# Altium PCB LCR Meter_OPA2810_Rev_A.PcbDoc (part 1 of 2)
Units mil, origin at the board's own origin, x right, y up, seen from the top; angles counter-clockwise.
Board outline 3760 x 2600 mil, 4 copper layers (L01_TOP, L02_GND, L03_PWR, L04_BOT), stack 62.234 mil thick; 153 components, 56 nets, 334 pads, 170 vias.
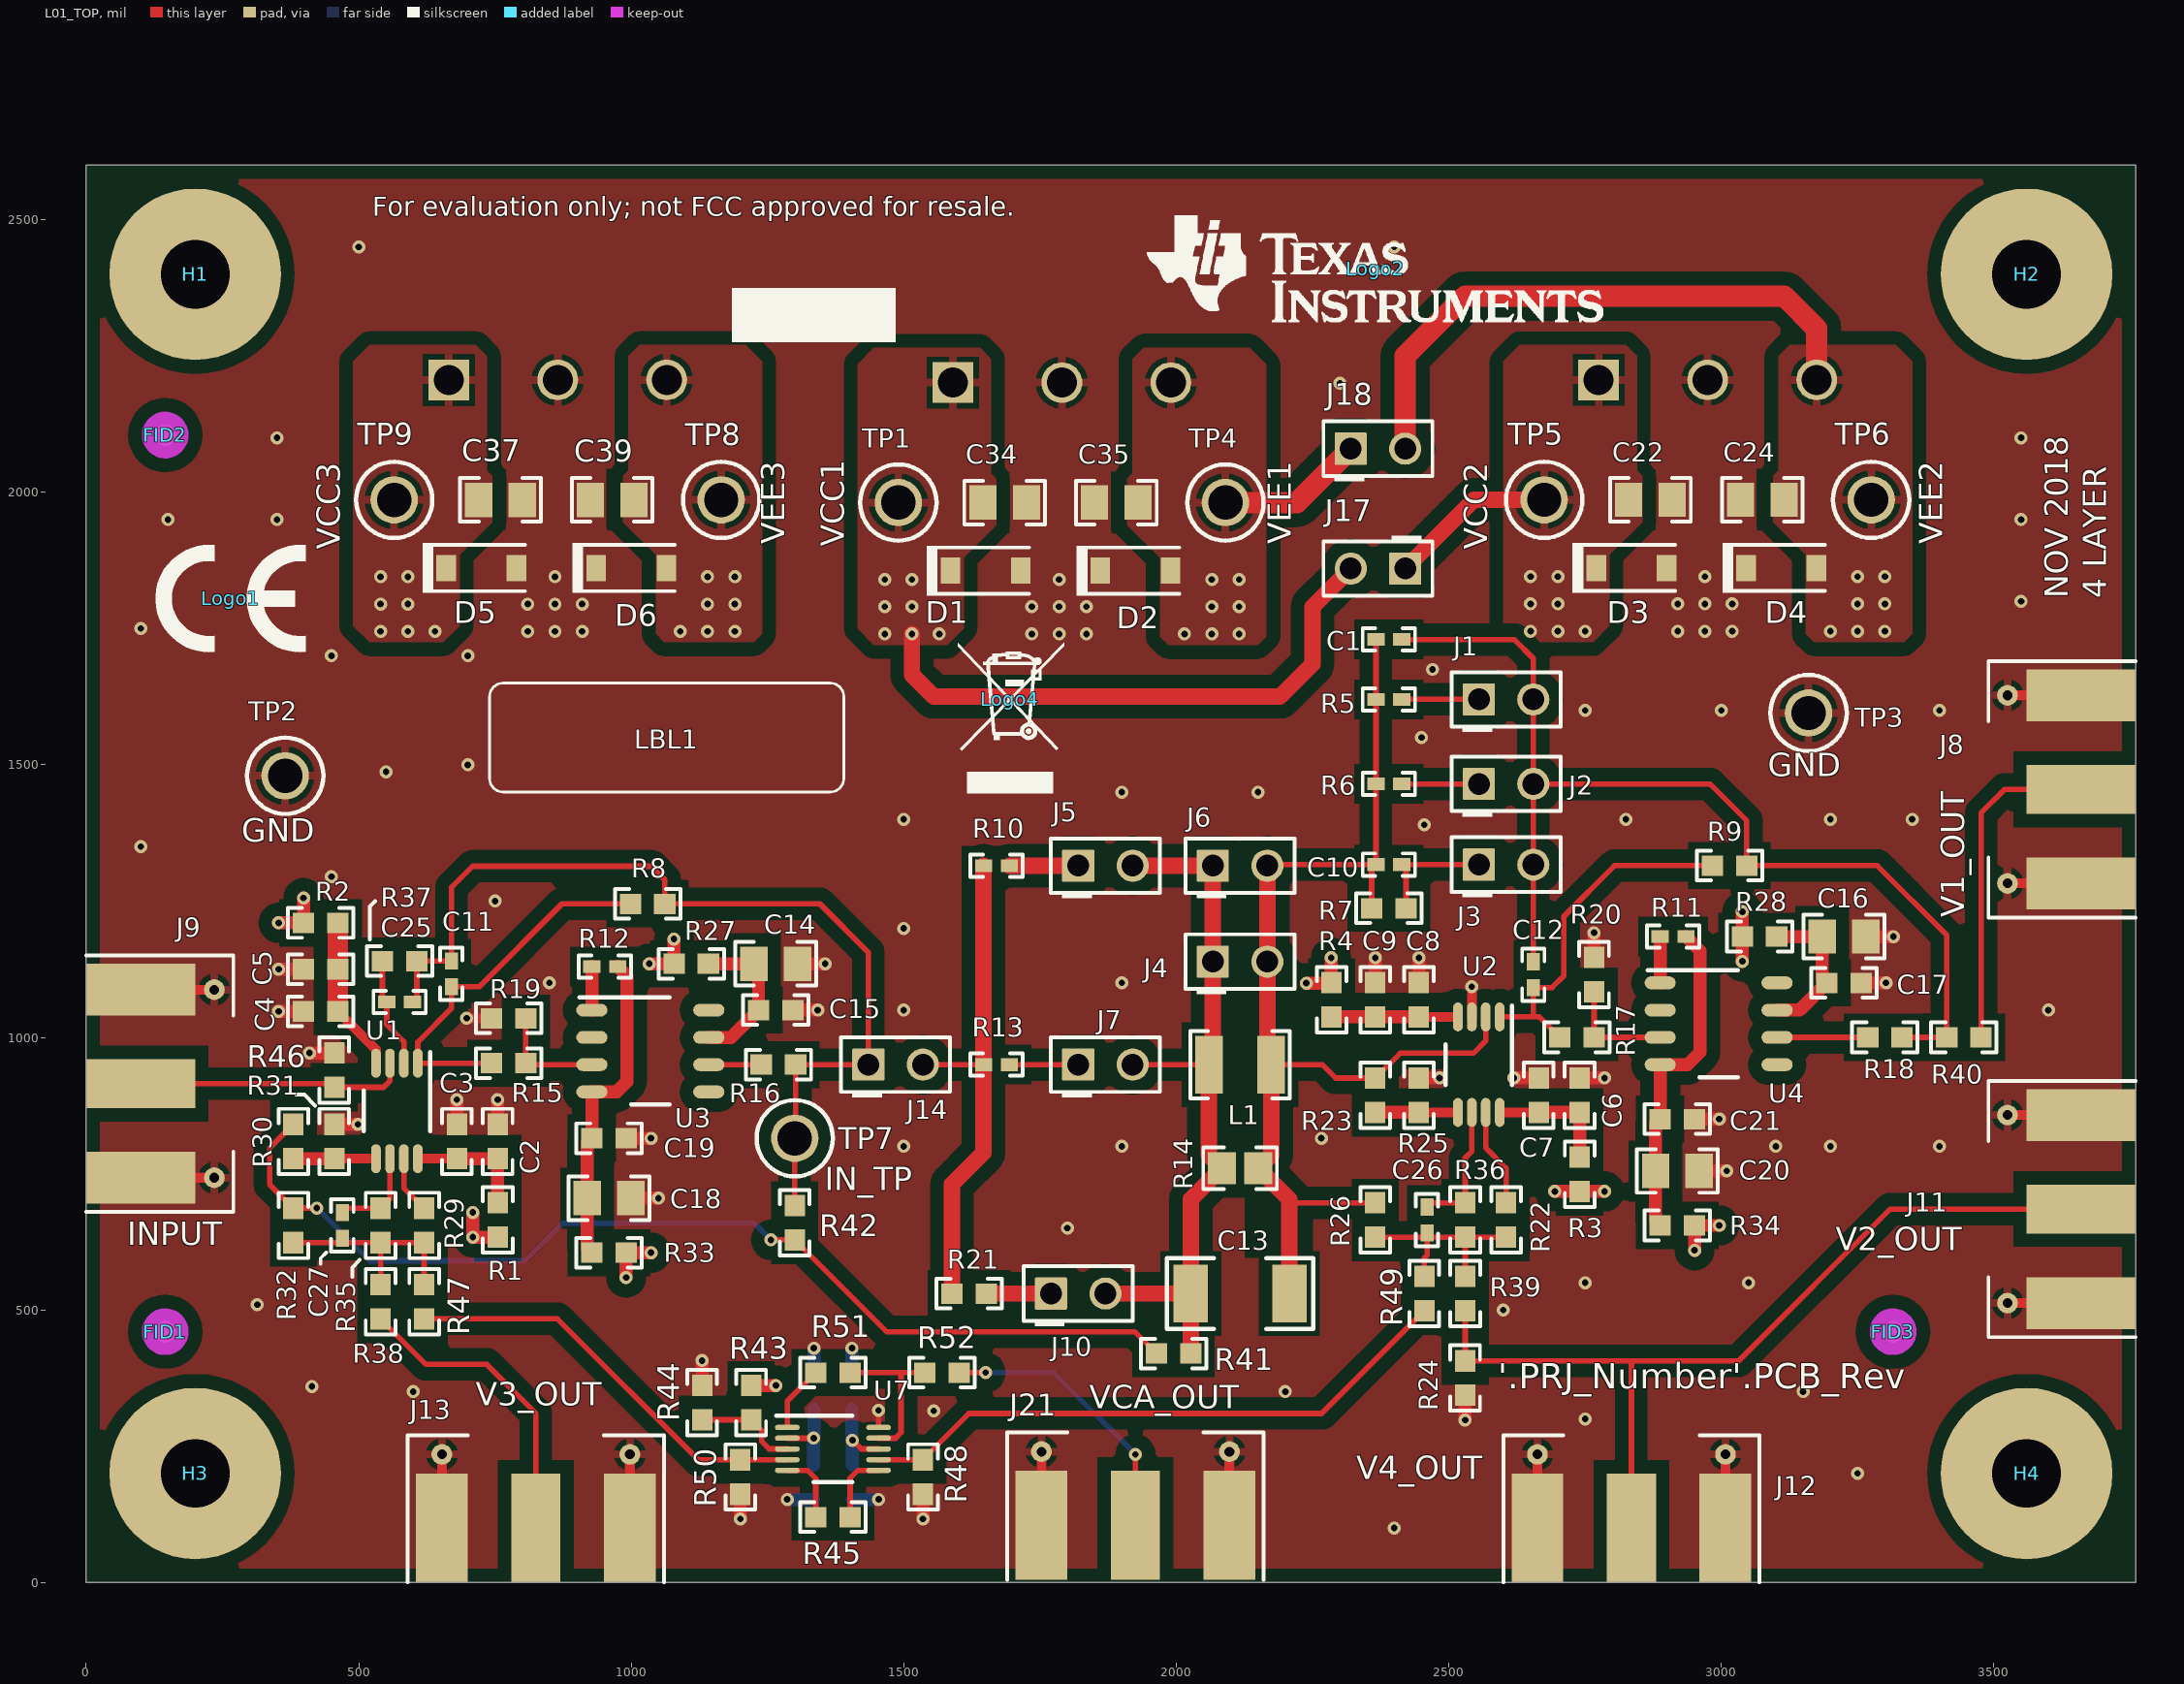
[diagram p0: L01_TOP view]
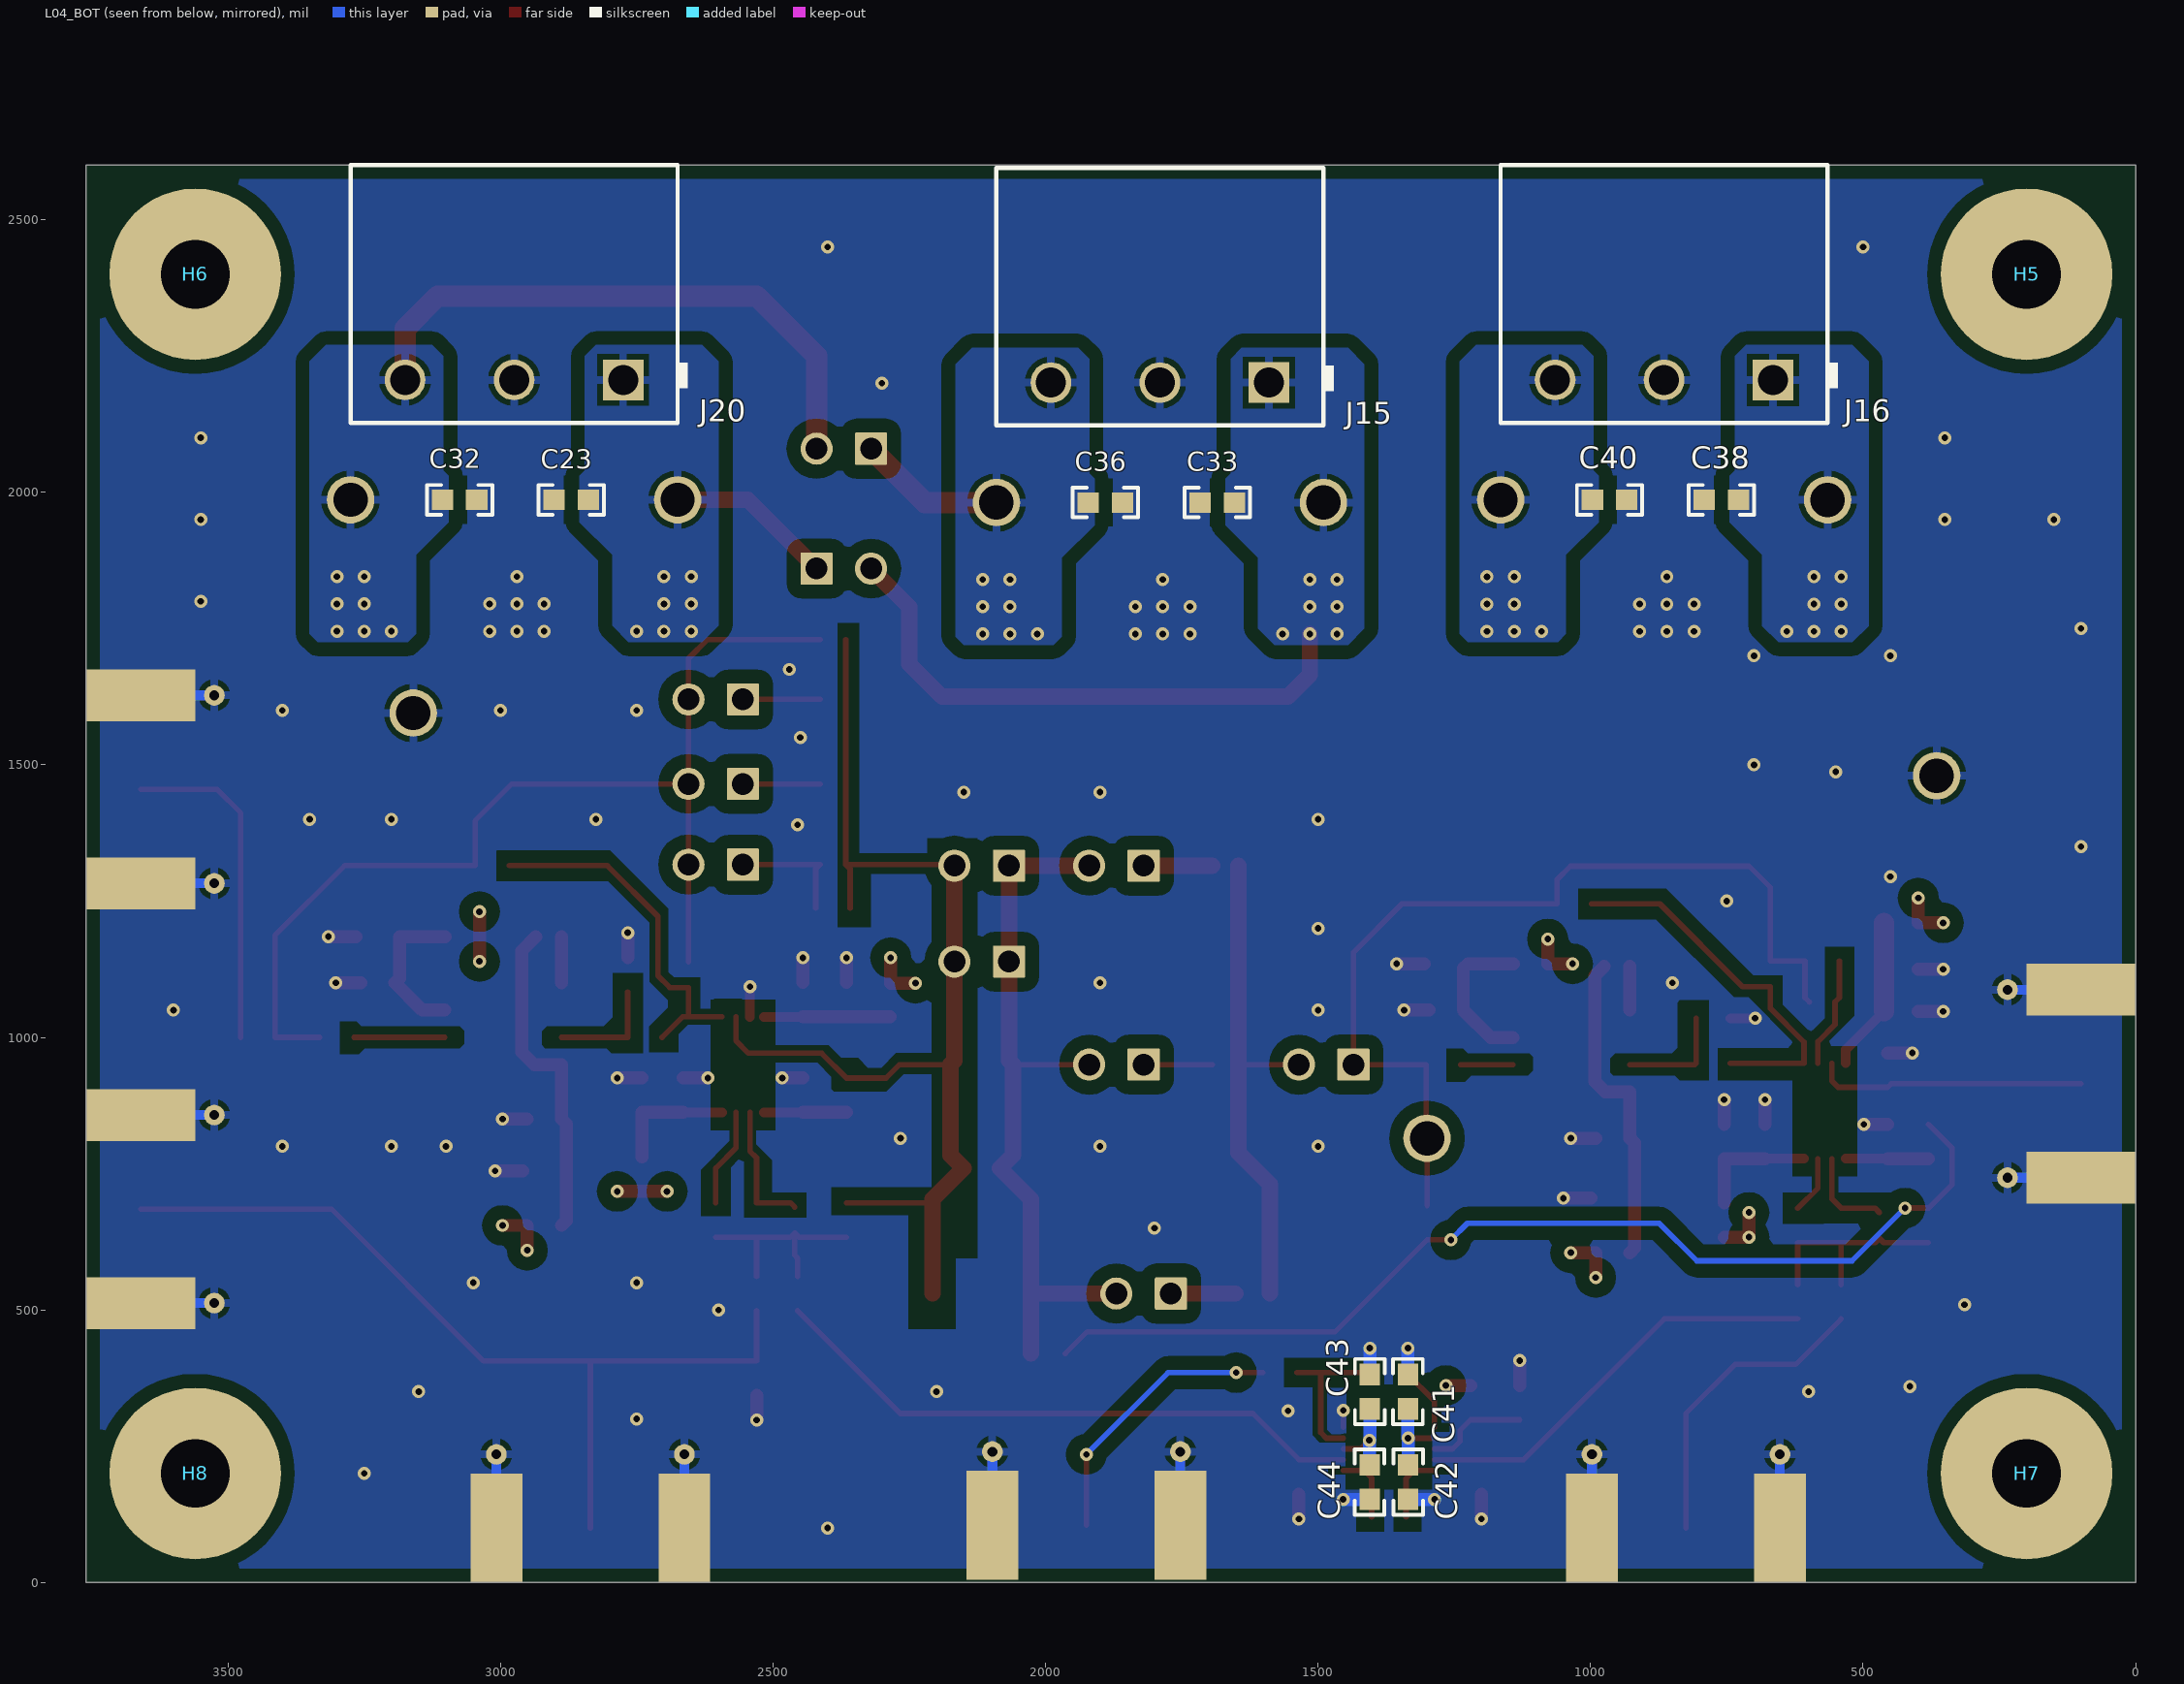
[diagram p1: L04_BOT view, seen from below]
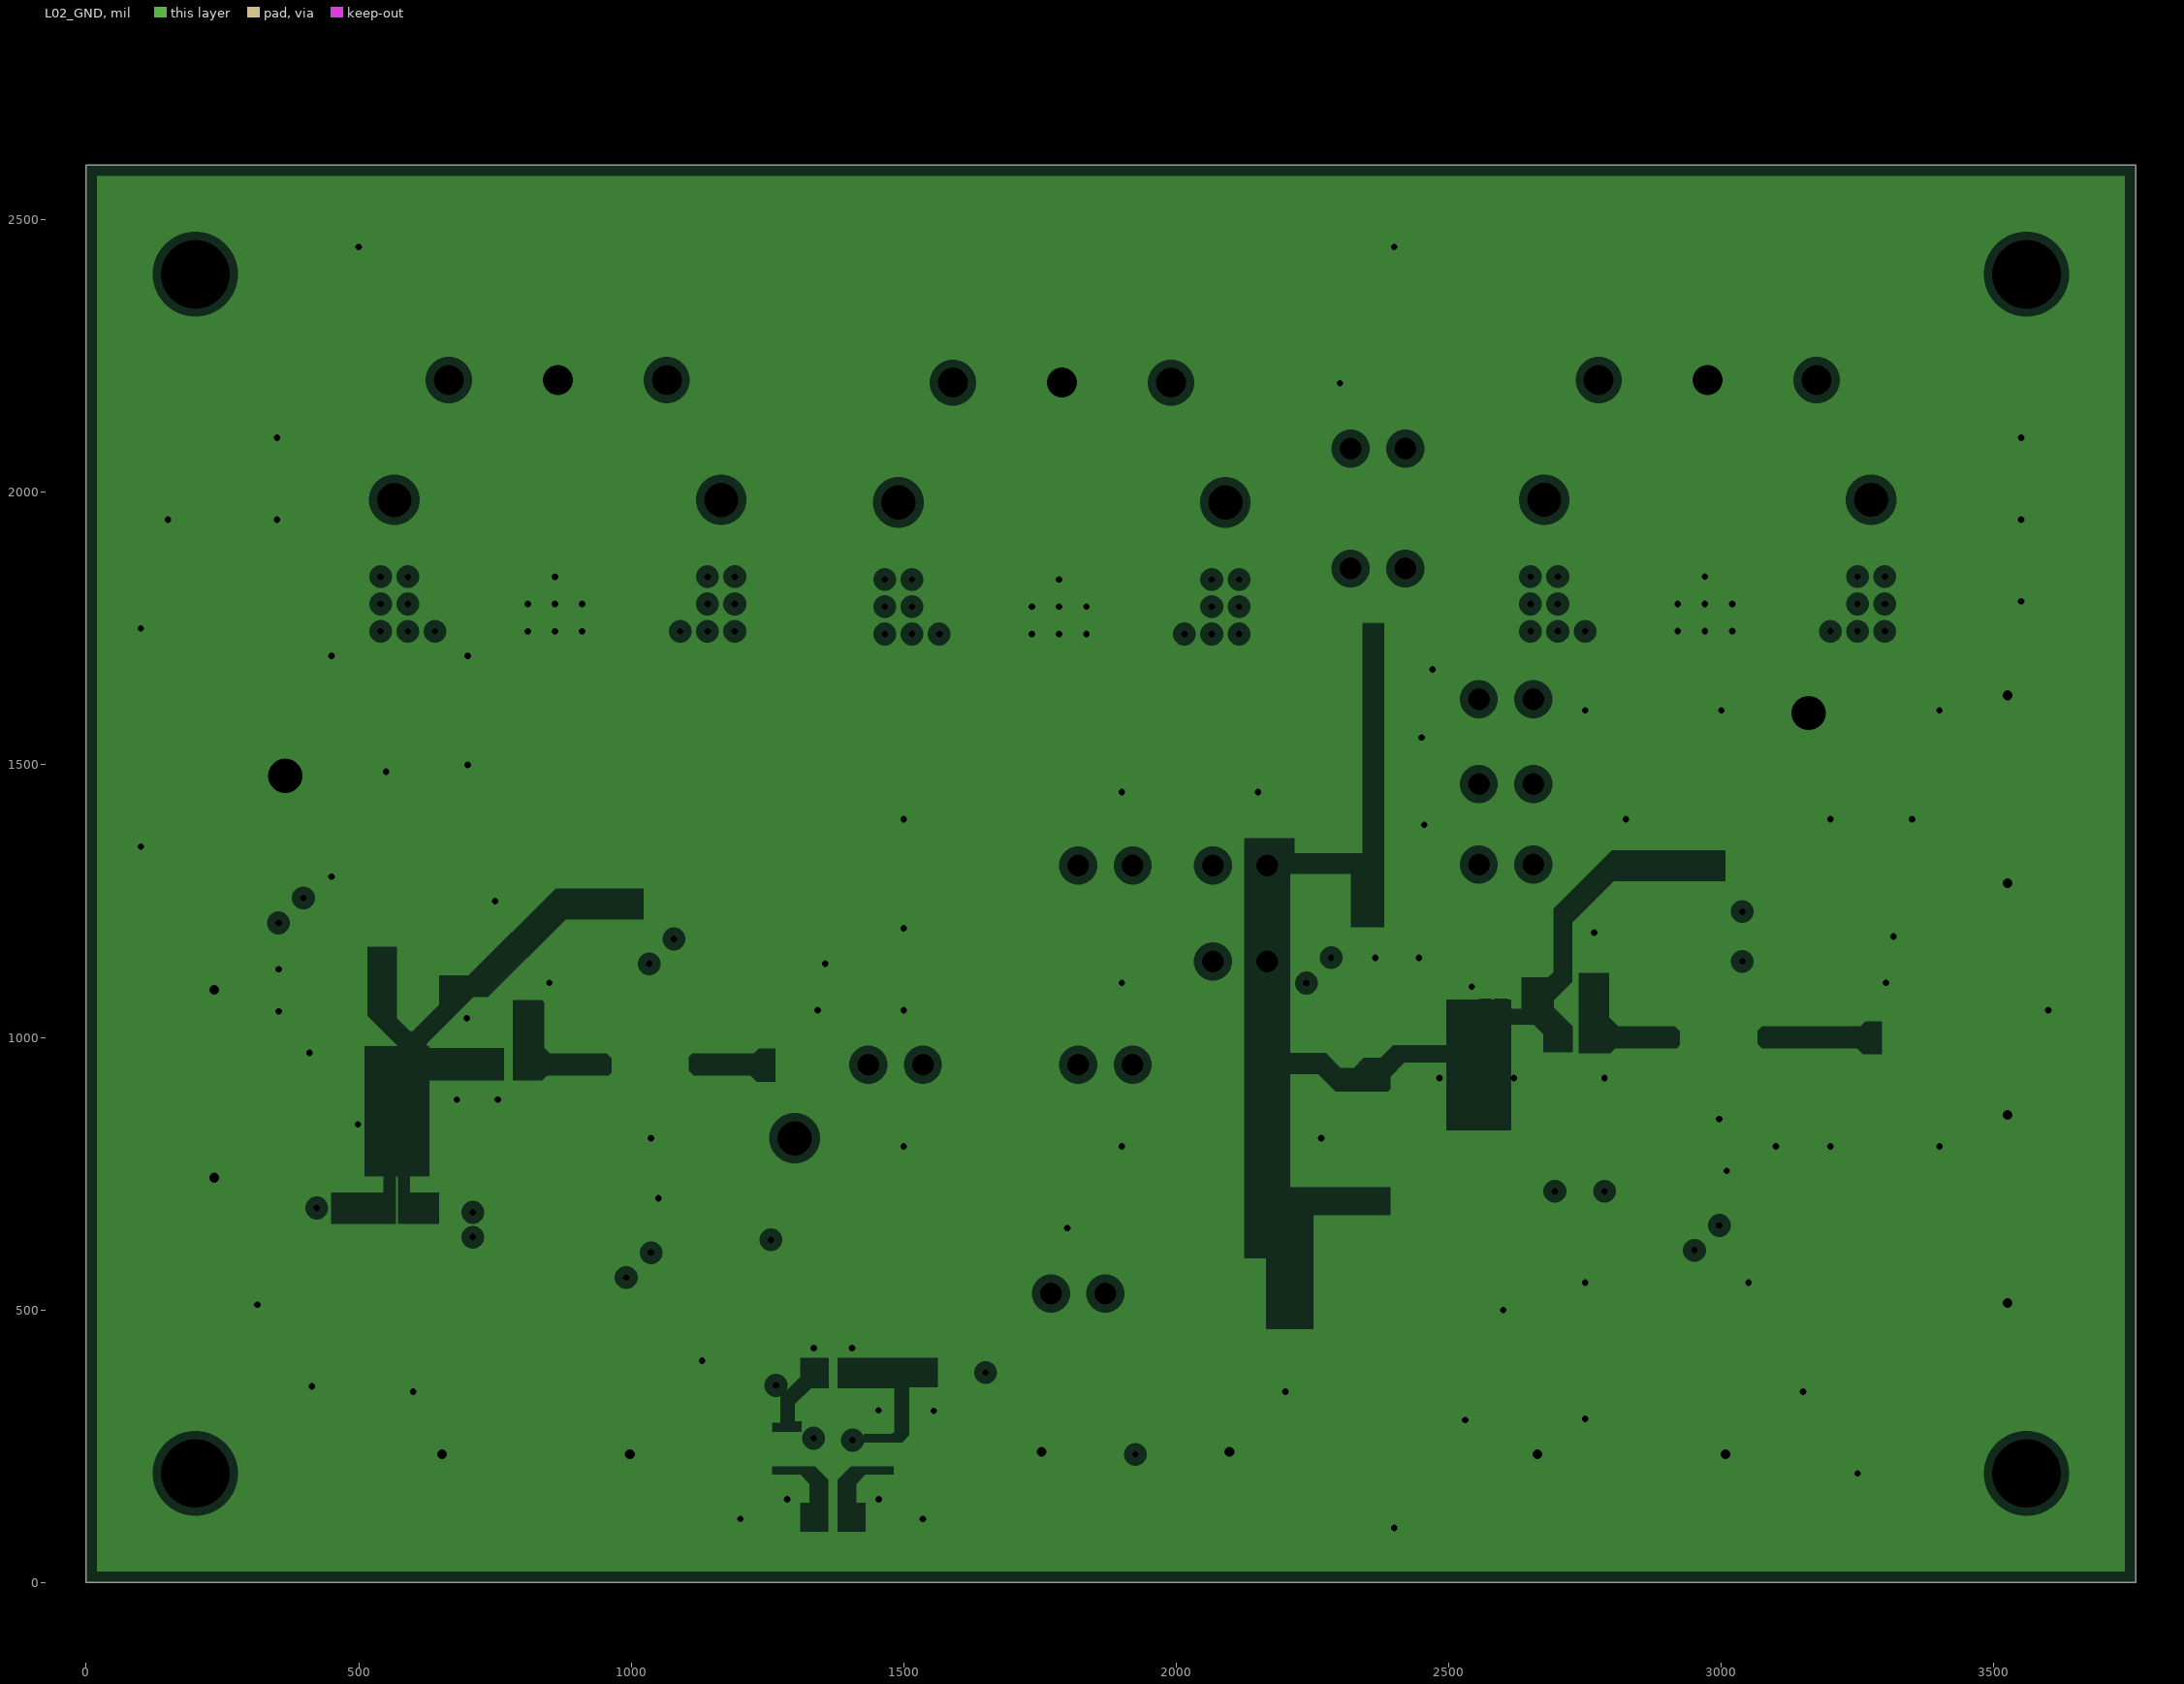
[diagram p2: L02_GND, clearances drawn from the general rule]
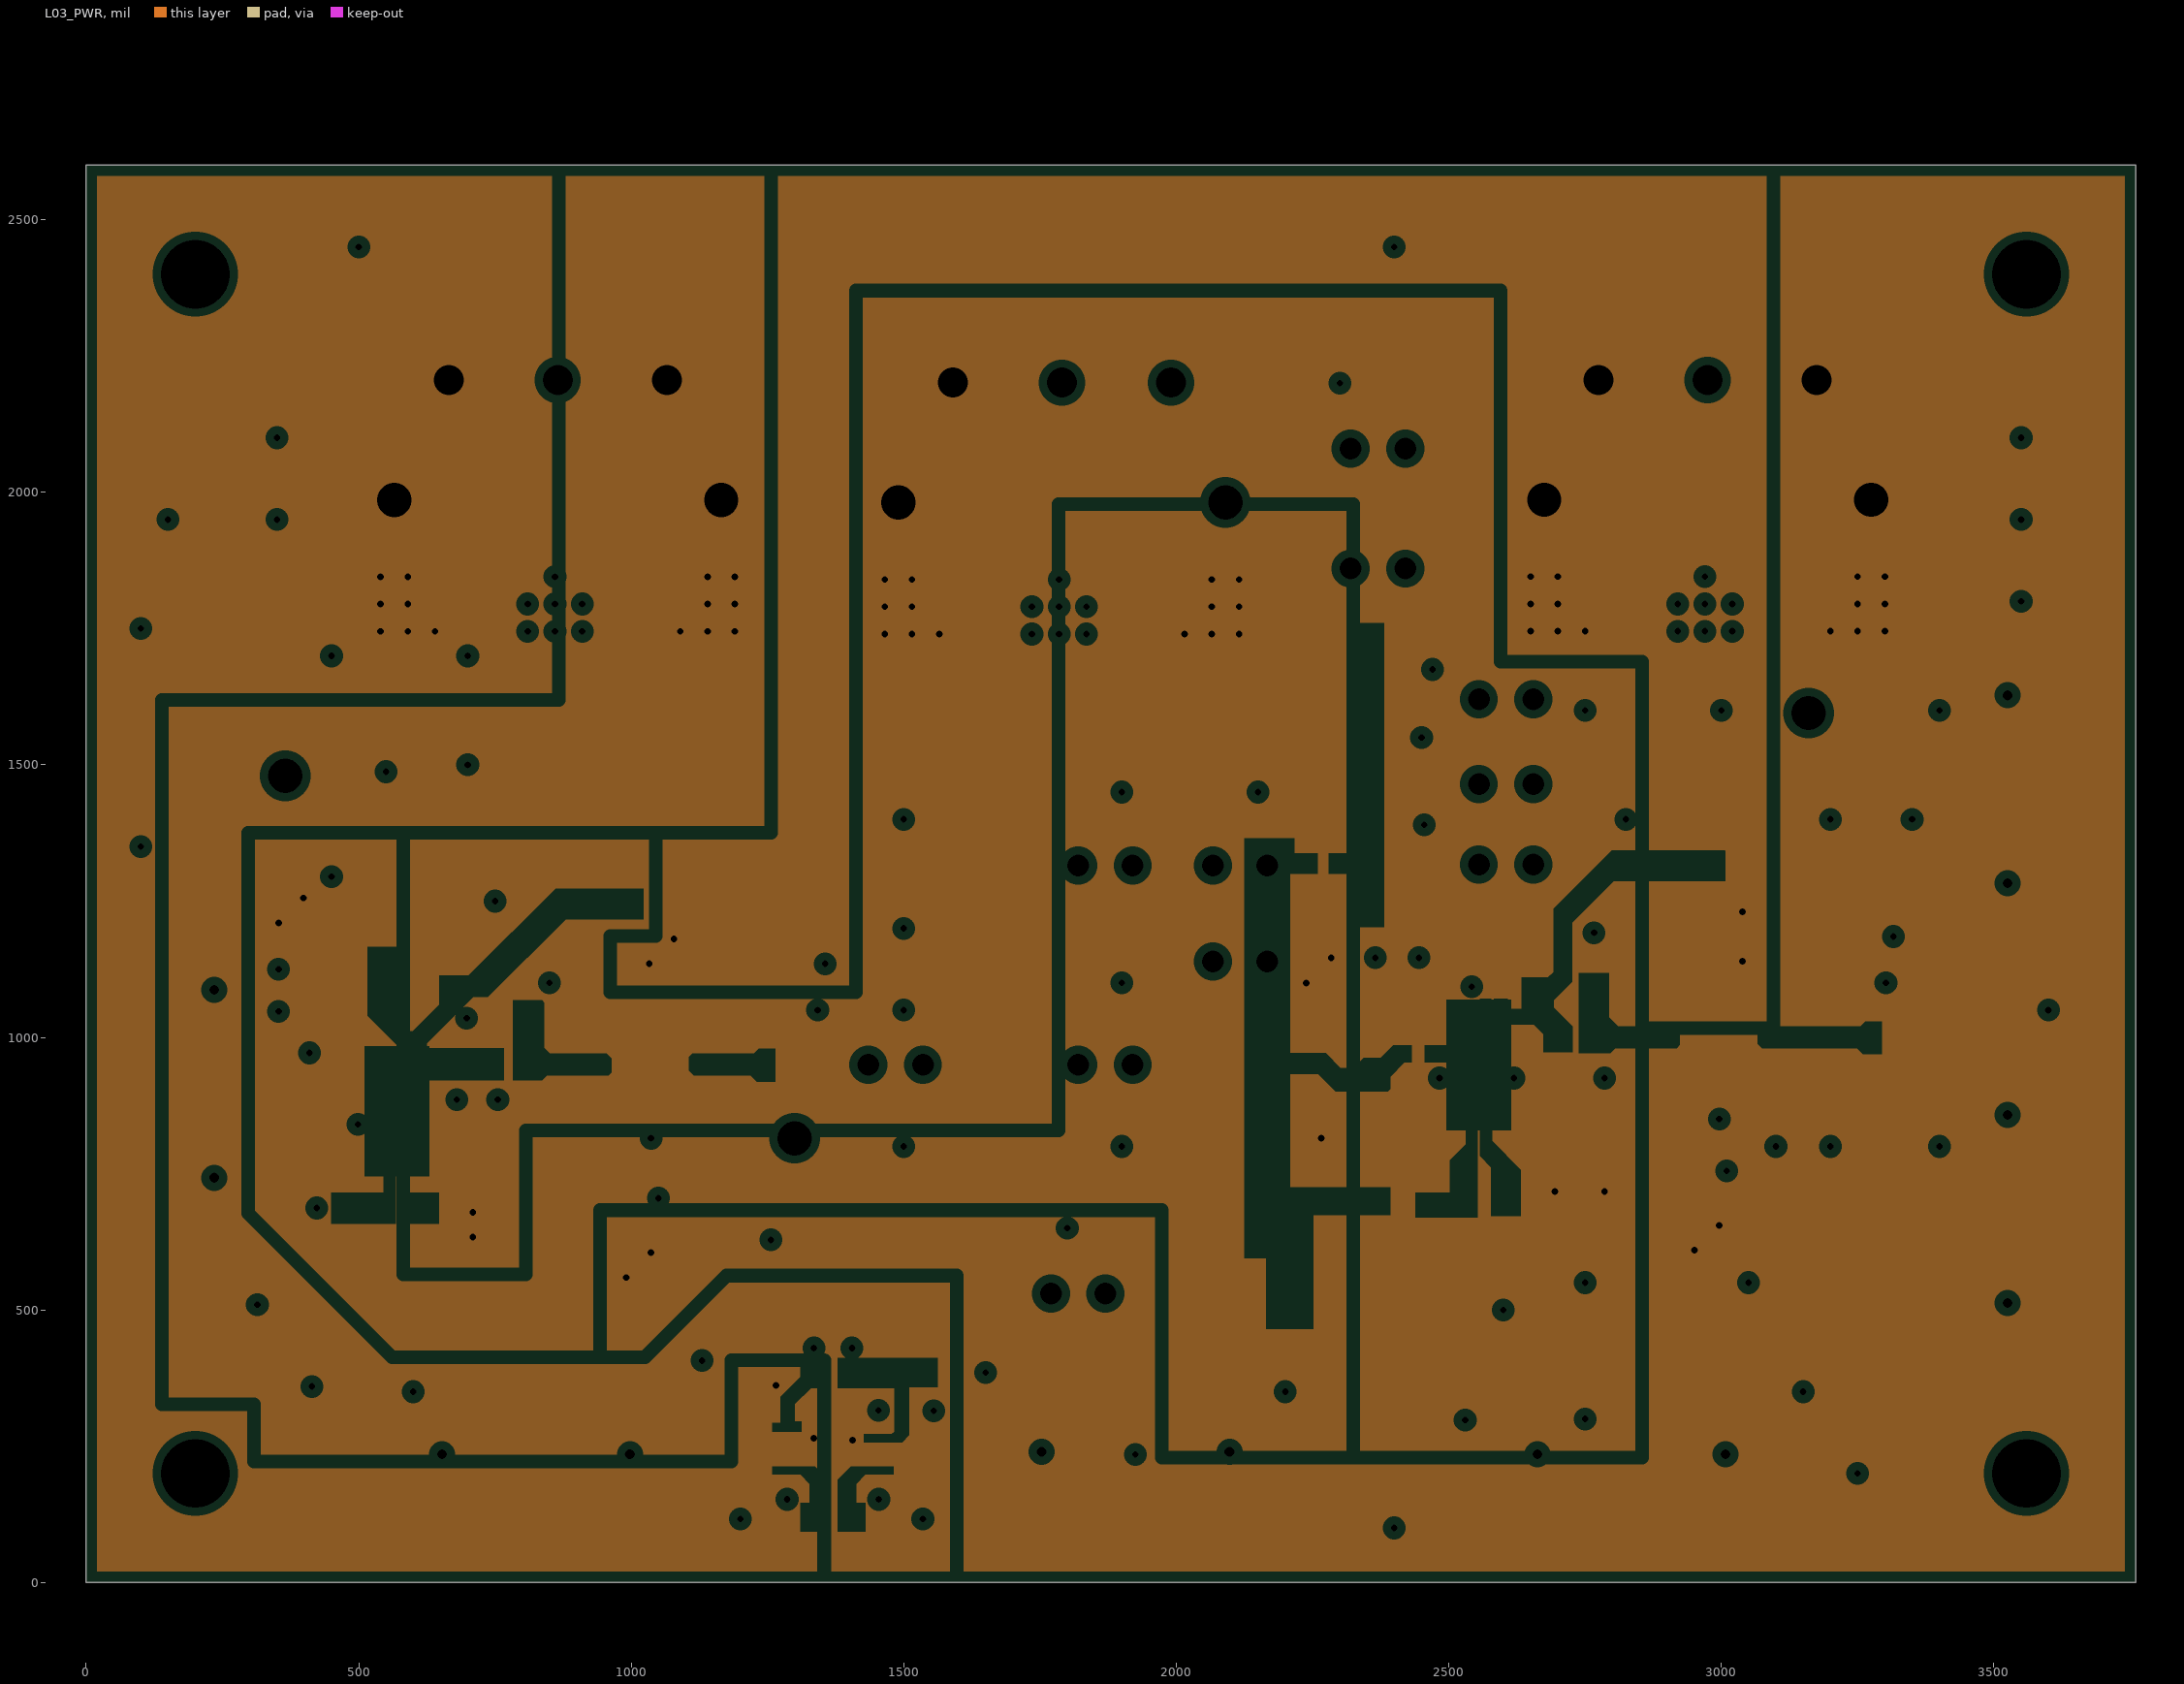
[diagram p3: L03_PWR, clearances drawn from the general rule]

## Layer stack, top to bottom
Top Solder: solder mask 0.4, Solder Resist, Dk 3.5
L01_TOP: signal copper 1.4
Dielectric 2: dielectric 10, Dk 4.2
L02_GND: plane copper 1.417, net GND
Dielectric1: core 36.6, FR-4, Dk 4.8
L03_PWR: plane copper 1.417
Dielectric 3: dielectric 10, Dk 4.2
L04_BOT: signal copper 1.4
Bottom Solder: solder mask 0.4, Solder Resist, Dk 3.5

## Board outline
0,0 3760,0 3760,2600 0,2600

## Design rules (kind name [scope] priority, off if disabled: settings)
AcuteAngle [All] p1: minimum=4.50000000000000E+0001 checktracksonly=FALSE
AssemblyTestPointUsage [All] p1: valid=2
BoardOutlineClearance BoardOutlineClearance_Board_Edge_Components [OnCopper and InComponentClass('Board_Edge_Component')] p1: gap=10 ignorepadtopadclearanceinfootprint=FALSE
BoardOutlineClearance BoardOutlineClearance_MountingHoles [OnCopper and InComponentClass('Mounting Holes')] p2: gap=40 ignorepadtopadclearanceinfootprint=FALSE
BoardOutlineClearance BoardOutlineClearance_Poly [OnCopper and IsPoly] p3: gap=25 ignorepadtopadclearanceinfootprint=FALSE
BoardOutlineClearance [OnCopper and Not InComponentClass('Logo') and not InComponentClass('FiducialMark') and not InRegion(1000,500,4000,800) and not InPoly   and Not InComponentClass('Board_Edge_Component')] p4: gap=40 ignorepadtopadclearanceinfootprint=FALSE
Clearance Clearance_Keepouts [((IsTrack Or IsArc) And Not InPoly) And IsFree and IsKeepOut vs ((IsTrack Or IsArc) And Not InPoly) And IsFree and IsKeepOut] p1: gap=0 ignorepadtopadclearanceinfootprint=FALSE
Clearance Clearance_Poly [InPolygon] p2: gap=25 ignorepadtopadclearanceinfootprint=FALSE except(0: Arc-Hole Track-Hole SMDPad-Hole THPad-Hole Via-Hole Fill-Hole Poly-Hole Region-Hole Text-Hole)
Clearance Clearance_FiducialMark [IsKeepOut and InComponentClass('FiducialMark') vs IsPad and InComponentClass('FiducialMark')] p3: gap=0 ignorepadtopadclearanceinfootprint=FALSE
Clearance [All] p4: gap=7.87 ignorepadtopadclearanceinfootprint=FALSE except(0: Arc-Hole Track-Hole SMDPad-Hole THPad-Hole Via-Hole Fill-Hole Poly-Hole Region-Hole Text-Hole)
ComponentClearance ComponentClearance_MountingHoles_FiducialMarks [InComponentClass('Mounting Holes') vs InComponentClass('FiducialMark')] p1: gap=50 collisioncheckmode=3 verticalgap=10 showdistances=FALSE
ComponentClearance ComponentClearance_Shunt [InComponentClass('Header') vs InComponentClass('Shunt')] p2: gap=0 collisioncheckmode=3 verticalgap=0 showdistances=FALSE
ComponentClearance ComponentClearance_Logo [InComponentClass('Logo')] p3: gap=50 collisioncheckmode=3 verticalgap=10 showdistances=FALSE
ComponentClearance ComponentClearance_ScrewToNut [(HasFootprint('NY PMS 440 0025 PH')) vs (HasFootprint('Keystone_1902C'))] p4: gap=5 collisioncheckmode=3 verticalgap=10 showdistances=FALSE
ComponentClearance ComponentClearance_MountingHoles [InComponentClass('Mounting Holes')] p5: gap=150 collisioncheckmode=3 verticalgap=100000 showdistances=FALSE
ComponentClearance ComponentClearance_SmallPassives [HasFootprint('0201*') or HasFootprint('0402*') or HasFootprint('0508') or HasFootprint('0603*') or HasFootprint('0612') or HasFootprint('0805*') or HasFootprint('0815*') or HasFootprint('0830*') or HasFootprint('1206*') or HasFootprint('1210*') or HasFootprint('1808*') or HasFootprint('1812*') or HasFootprint('1825*') or HasFootprint('2010*') or HasFootprint('2220*') or HasFootprint('2225*') or HasFootprint('2512*') or HasFootprint('2728*') or HasFootprint('3518*') vs HasFootprint('0201*') or HasFootprint('0402*') or HasFootprint('0508') or HasFootprint('0603*') or HasFootprint('0612') or HasFootprint('0805*') or HasFootprint('0815*') or HasFootprint('0830*') or HasFootprint('1206*') or HasFootprint('1210*') or HasFootprint('1808*') or HasFootprint('1812*') or HasFootprint('1825*') or HasFootprint('2010*') or HasFootprint('2220*') or HasFootprint('2225*') or HasFootprint('2512*') or HasFootprint('2728*') or HasFootprint('3518*')] p6: gap=14.96 collisioncheckmode=3 verticalgap=10 showdistances=FALSE
ComponentClearance ComponentClearance_THtoSMT [IsThruComponent vs IsSMTComponent] p7: gap=40 collisioncheckmode=3 verticalgap=30 showdistances=FALSE
ComponentClearance ComponentClearance_THtoTH [IsThruComponent vs IsThruComponent] p8: gap=30 collisioncheckmode=3 verticalgap=30 showdistances=FALSE
ComponentClearance [All] p9: gap=30 collisioncheckmode=3 verticalgap=10 showdistances=FALSE
DiffPairsRouting [All] p1: maxlimit=100 minlimit=10 mostfreqgap=10 toplayer_minwidth=15 toplayer_maxwidth=15 toplayer_prefwidth=15 bottomlayer_minwidth=15 bottomlayer_maxwidth=15 bottomlayer_prefwidth=15 maxuncoupledlength=1000
FabricationTestPointUsage TestPointUsage [All] p1: valid=2 allowmultiple=FALSE
FabricationTestpoint Testpoint [All] p1: side=3 testpointundercomponent=TRUE minsize=40 maxsize=100 preferedsize=60 minholesize=0 maxholesize=40 preferedholesize=32 testpointgrid=1 allowsidetop=TRUE allowsidebottom=TRUE usegrid=TRUE gridtolerance=0.01
FanoutControl Fanout_LCC [IsLCC] p1: bgadir=Out bgaviamode=Centered fanoutstyle=Auto fanoutdirection=Alternating viagrid=1 // Fanout_LCC (Default Rule)
FanoutControl Fanout_BGA [IsBGA] p2: bgadir=Out bgaviamode=Centered fanoutstyle=Auto fanoutdirection=Alternating viagrid=1 // Fanout_BGA (Default Rule)
FanoutControl Fanout_Default [All] p4: bgadir=Out bgaviamode=Centered fanoutstyle=Auto fanoutdirection=Alternating viagrid=1 // Fanout_Default (Default Rule)
FanoutControl Fanout_Small [(CompPinCount < 5)] p5: bgadir=Out bgaviamode=Centered fanoutstyle=Auto fanoutdirection=OutThenIn viagrid=1 // Fanout_Small (Default Rule)
HoleSize [All] p1: absolutevalues=TRUE maxlimit=251 minlimit=7.87 maxpercent=80.000 minpercent=20.000
MinimumAnnularRing MinimumAnnularRing_ThermalPadVias [IsVia and InAnyComponent] p1: minimumring=5
MinimumAnnularRing [All] p2: minimumring=5
MinimumSolderMaskSliver MinimumSolderMaskSliver_Logo [InComponentClass('Logo') vs InComponentClass('Logo')] p1: minsoldermaskwidth=0.7
MinimumSolderMaskSliver [All] p2: minsoldermaskwidth=3.94
PlaneClearance [All] p1: clearance=15
PlaneConnect [All] p1: pad.planeconnectstyle=Relief pad.reliefexpansion=10 pad.reliefentries=4 pad.reliefconductorwidth=15 pad.reliefairgap=10 via.planeconnectstyle=Direct via.reliefexpansion=10 via.reliefentries=4 via.reliefconductorwidth=10 via.reliefairgap=10
PolygonConnect [All] p1: thpad.connectstyle=Relief thpad.reliefconductorwidth=15 thpad.reliefentries=4 thpad.polygonreliefangle="90 Angle" thpad.airgapwidth=10 smdpad.connectstyle=Direct smdpad.reliefconductorwidth=10 smdpad.reliefentries=4 smdpad.polygonreliefangle="90 Angle" smdpad.airgapwidth=10 via.connectstyle=Direct via.reliefconductorwidth=10 via.reliefentries=4 via.polygonreliefangle="90 Angle" via.airgapwidth=10
RoutingVias ThermalPadVias [IsVia and InAnyComponent] p1: holewidth=7.87 width=19.68 viastyle="Through Hole" minholewidth=7.87 minwidth=19.68 maxholewidth=12.99 maxwidth=23.62
RoutingVias [All] p2: holewidth=12 width=24 viastyle="Through Hole" minholewidth=12 minwidth=24 maxholewidth=12 maxwidth=24
SilkToBoardRegionClearance [Not ((IsComment or IsDesignator) And (Hide <> 'False')) and not InRegion(1000,500,4000,800)] p1:
SilkToSilkClearance SilkToSilkClearance_Pb-FreeLogo [(HasFootprint('Pb-Free_Overlay_Medium') OR HasFootprint('Pb-Free_Overlay_Small')) vs (HasFootprint('Pb-Free_Overlay_Medium') OR HasFootprint('Pb-Free_Overlay_Small'))] p1: silktosilkclearance=0
SilkToSilkClearance [All] p2: silktosilkclearance=4
SilkToSolderMaskClearance SilkToComponentPadClearance [(IsPad or IsFill or IsRegion) and InAnycomponent] p1: minsilkscreentomaskgap=5 clearancetoexposedcopper=TRUE
SilkToSolderMaskClearance "Silk to Solder Mask Opening" [All] p2: minsilkscreentomaskgap=4 clearancetoexposedcopper=FALSE
SolderMaskExpansion [All] p1: expansion=1.97
Width [All] p1: maxlimit=100 minlimit=6 preferedwidth=10 checkconnectedcopper=TRUE
14 further rules are at their usual default settings.

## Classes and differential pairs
component class Label: LBL1
component class AssemblyNote: ZZ1 ZZ2 ZZ3 ZZ4
component class FiducialMark: FID1 FID2 FID3
component class EVM_Hardware: FID1 FID2 FID3 H1 H2 H3 H4 H5 H6 H7 H8 LBL1 Logo1 Logo2 Logo3 Logo4 ZZ1 ZZ2 ZZ3 ZZ4
component class Logo: Logo2
component class "Mounting Holes": H1 H2 H3 H4
component class BlankSheet: C1 C2 C3 C4 C5 C6 C7 C8 C9 C10 C11 C12 C13 C14 C15 C16 C17 C18 C19 C20 C21 C25 C26 C27 J1 J2 J3 J4 J5 J6 J7 J8 J9 J10 J11 J12 J13 J14 L1 R1 R2 R3 R4 R5 R6 R7 R8 R9 R10 R11 R12 R13 R14 R15 R16 R17 R18 R19 R20 R21 R22 R23 R24 R25 R26 R27 R28 R29 R30 R31 R32 R33 R34 R35 R36 R37 R38 R39 R40 R41 R42 R46 TP7 U1 U2 U3 U4
component class Header: J1 J2 J3 J4 J5 J6 J7 J10 J14 J17 J18
component class "Power Supply": C22 C23 C24 C32 C33 C34 C35 C36 C37 C38 C39 C40 D1 D2 D3 D4 D5 D6 J15 J16 J17 J18 J20 TP1 TP2 TP3 TP4 TP5 TP6 TP8 TP9
component class VCA: C41 C42 C43 C44 J21 R43 R44 R45 R47 R48 R49 R50 R51 R52 U7

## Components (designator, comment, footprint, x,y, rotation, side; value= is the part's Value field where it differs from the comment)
C1 "GRM1555C1H5R0CA01D" 0402 2390,1730 r180 top value=5pF
C2 "C1608X7R1V105K080AC" 0603 755,808.9 r90 top value=1uF
C3 "GRM188R71H104KA93D" 0603 680,808.9 r90 top value=0.1uF
C4 "GRM188R71H104KA93D" 0603 430,1047.6 r180 top value=0.1uF
C5 "C1608X7R1V105K080AC" 0603 430,1125 r180 top value=1uF
C6 "C1608X7R1V105K080AC" 0603 2740,893.9 r90 top value=1uF
C7 "GRM188R71H104KA93D" 0603 2665,893.9 r90 top value=0.1uF
C8 "GRM188R71H104KA93D" 0603 2445,1069.09 r90 top value=0.1uF
C9 "C1608X7R1V105K080AC" 0603 2365,1069.09 r90 top value=1uF
C10 "GRM1555C1H5R0CA01D" 0402 2390,1316.98 r180 top value=5pF
C11 "GRM1555C1H5R0CA01D" 0402 670,1116.38 r90 top value=5pF
C12 "GRM1555C1H5R0CA01D" 0402 2655,1115 r270 top value=5pF
C13 "Used in BOM report" 2010 2117,530 r180 top
C14 "GRM21BC8YA106KE11L" 0805_HV 1265,1135 r0 top value=10uF
C15 "GRM188R71H104KA93D" 0603 1265,1050 r0 top value=0.1uF
C16 "GRM21BC8YA106KE11L" 0805_HV 3225,1185 r0 top value=10uF
C17 "GRM188R71H104KA93D" 0603 3225,1100 r0 top value=0.1uF
C18 "GRM21BC8YA106KE11L" 0805_HV 959.21,705 r180 top value=10uF
C19 "GRM188R71H104KA93D" 0603 959.21,815 r180 top value=0.1uF
C20 "GRM21BC8YA106KE11L" 0805_HV 2919.22,755.01 r180 top value=10uF
C21 "GRM188R71H104KA93D" 0603 2919.21,850 r180 top value=0.1uF
C22 "GRM21BC8YA106KE11L" 0805_HV 2870,1986.21 r0 top value=10uF
C23 "C1608X7R1V105K080AC" 0603 2870,1986.21 r0 bottom value=1uF
C24 "GRM21BC8YA106KE11L" 0805_HV 3075,1986.21 r180 top value=10uF
C25 "GRM1555C1H5R0CA01D" 0402 575,1065 r180 top value=5pF
C26 "GRM1555C1H5R0CA01D" 0402 2460,665 r90 top value=5pF
C27 "GRM1555C1H5R0CA01D" 0402 470,655 r90 top value=5pF
C32 "C1608X7R1V105K080AC" 0603 3075,1986.21 r0 bottom value=1uF
C33 "C1608X7R1V105K080AC" 0603 1685.01,1981.12 r180 bottom value=1uF
C34 "GRM21BC8YA106KE11L" 0805_HV 1685.01,1981.13 r0 top value=10uF
C35 "GRM21BC8YA106KE11L" 0805_HV 1890.01,1981.13 r180 top value=10uF
C36 "C1608X7R1V105K080AC" 0603 1890.01,1981.12 r0 bottom value=1uF
C37 "GRM21BC8YA106KE11L" 0805_HV 760,1986.13 r0 top value=10uF
C38 "C1608X7R1V105K080AC" 0603 760,1986.13 r180 bottom value=1uF
C39 "GRM21BC8YA106KE11L" 0805_HV 965,1986.13 r180 top value=10uF
C40 "C1608X7R1V105K080AC" 0603 965,1986.13 r0 bottom value=1uF
C41 "GRM188R71H104KA93D" 0603 1335,350 r90 bottom value=0.1uF
C42 "C1608X7R1V105K080AC" 0603 1334.57,183.98 r90 bottom value=1uF
C43 "GRM188R71H104KA93D" 0603 1405,350 r90 bottom value=0.1uF
C44 "C1608X7R1V105K080AC" 0603 1405.43,183.98 r90 bottom value=1uF
D1 "MMSZ4701T1G" SOD-123 1650.01,1856.13 r0 top value=14V
D2 "MMSZ4701T1G" SOD-123 1925.01,1856.13 r0 top value=14V
D3 "MMSZ4705T1G" SOD-123 2835,1861.21 r0 top value=18V
D4 "MMSZ4705T1G" SOD-123 3110,1861.21 r0 top value=18V
D5 "MMSZ4701T1G" SOD-123 725,1861.13 r0 top value=14V
D6 "MMSZ4701T1G" SOD-123 1000,1861.13 r0 top value=14V
FID1 "Fiducial" Fiducial10-20 145,460 r0 top
FID2 "Fiducial" Fiducial10-20 145,2105 r0 top
FID3 "Fiducial" Fiducial10-20 3315,460 r0 top
H1 "NY PMS 440 0025 PH" "NY PMS 440 0025 PH" 200,2400 r0 top locked
H2 "NY PMS 440 0025 PH" "NY PMS 440 0025 PH" 3560,2400 r0 top locked
H3 "NY PMS 440 0025 PH" "NY PMS 440 0025 PH" 200,200 r0 top locked
H4 "NY PMS 440 0025 PH" "NY PMS 440 0025 PH" 3560,200 r0 top locked
H5 "1902C" Keystone_1902C 200,2400 r180 bottom locked
H6 "1902C" Keystone_1902C 3560,2400 r180 bottom locked
H7 "1902C" Keystone_1902C 200,200 r180 bottom locked
H8 "1902C" Keystone_1902C 3560,200 r180 bottom locked
J1 "PEC02SAAN" CONN_PEC02SAAN 2605,1620 r0 top
J2 "PEC02SAAN" CONN_PEC02SAAN 2605,1465 r0 top
J3 "PEC02SAAN" CONN_PEC02SAAN 2605,1316.98 r0 top
J4 "PEC02SAAN" CONN_PEC02SAAN 2117,1139 r0 top
J5 "PEC02SAAN" CONN_PEC02SAAN 1870,1315 r0 top
J6 "PEC02SAAN" CONN_PEC02SAAN 2117,1315 r0 top
J7 "PEC02SAAN" CONN_PEC02SAAN 1870,950 r0 top
J8 "V1_OUT" Johnson_142-0701-80x 3660,1455 r270 top
J9 "142-0701-806" Johnson_142-0701-80x 100,915 r90 top
J10 "PEC02SAAN" CONN_PEC02SAAN 1820,530 r0 top
J11 "V2_OUT" Johnson_142-0701-80x 3660,685 r270 top
J12 "V4_OUT" Johnson_142-0701-80x 2835,100 r180 top
J13 "V3_OUT" Johnson_142-0701-80x 825,100 r180 top
J14 "PEC02SAAN" CONN_PEC02SAAN 1485,950 r0 top
J15 "1759020" Phoenix_1759020 1790.01,2201.13 r0 bottom
J16 "1759020" Phoenix_1759020 865,2206.13 r0 bottom
J17 "PEC02SAAN" CONN_PEC02SAAN 2370,1860 r180 top
J18 "PEC02SAAN" CONN_PEC02SAAN 2370,2080 r0 top
J20 "1759020" Phoenix_1759020 2975,2206.21 r0 bottom
J21 "VCA_OUT" Johnson_142-0701-80x 1925.01,105 r180 top
L1 "Used in BOM report" 1210 2117,950 r0 top
LBL1 "THT-14-423-10" Label_650x200 1065,1550 r0 top
Logo1 "CE Mark" CE_Mark_5mm 265,1805 r0 top
Logo2 "Texas Instruments" TI_Stacked_Overlay_Small 2365,2410 r0 top
Logo3 "FCC disclaimer" FCC_disclaimer 2520,5935 r0 top
Logo4 "WEEE logo" WEEE_Minimum 1695,1620 r0 top
R1 "RC0603JR-070RL" 0603 755,665 r270 top value=0
R2 "RC0603JR-070RL" 0603 430,1210 r180 top value=0
R3 "RC0603JR-070RL" 0603 2740,748.9 r270 top value=0
R4 "RC0603JR-070RL" 0603 2285,1069.09 r90 top value=0
R5 "RG1005P-101-B-T5" 0402 2390,1620 r0 top value=100
R6 "PNM0402E5001BST1" 0402 2390,1465 r0 top value=5.00k
R7 "RG1608P-104-B-T5" 0603 2390,1236.98 r0 top value=100k
R8 "RC0603JR-070RL" 0603 1030,1245 r0 top value=0
R9 "RC0603JR-070RL" 0603 3015,1315 r0 top value=0
R10 "RG1005P-101-B-T5" 0402 1670,1315 r0 top value=100
R11 "PNM0402E5001BST1" 0402 2911.34,1185 r0 top value=5.00k
R12 "PNM0402E5001BST1" 0402 951.34,1130 r0 top value=5.00k
R13 "PNM0402E5001BST1" 0402 1670,950 r0 top value=5.00k
R14 "Used in BOM report" 0805 2117,760 r0 top
R15 "RC0603JR-070RL" 0603 775,952.6 r0 top value=0
R16 "RC0603JR-070RL" 0603 1270,950 r0 top value=0
R17 "RC0603JR-070RL" 0603 2735,1000 r0 top value=0
R18 "RC0603JR-070RL" 0603 3300,1000 r0 top value=0
R19 "RC0603JR-070RL" 0603 775,1035 r0 top value=0
R20 "RC0603JR-070RL" 0603 2766.5,1115 r270 top value=0
R21 "RG1608P-104-B-T5" 0603 1620,530 r0 top value=100k
R22 "RC0603JR-070RL" 0603 2605,665 r270 top value=0
R23 "RC0603JR-070RL" 0603 2365,893.9 r270 top value=0
R24 "RC0603JR-070RL" 0603 2530,375 r90 top value=0
R25 "RC0603JR-070RL" 0603 2445,893.9 r270 top value=0
R26 "RC0603JR-070RL" 0603 2365,665 r270 top value=0
R27 "RC0603JR-070RL" 0603 1110,1135 r180 top value=0
R28 "RC0603JR-070RL" 0603 3070,1185 r180 top value=0
R29 "RC0603JR-070RL" 0603 620,655 r270 top value=0
R30 "RC0603JR-070RL" 0603 380,808.9 r270 top value=0
R31 "RC0603JR-070RL" 0603 455,808.9 r270 top value=0
R32 "RC0603JR-070RL" 0603 380,655 r270 top value=0
R33 "RC0603JR-070RL" 0603 959.21,605 r180 top value=0
R34 "RC0603JR-070RL" 0603 2919.22,655.01 r180 top value=0
R35 "RC0603JR-070RL" 0603 540,655 r270 top value=0
R36 "RC0603JR-070RL" 0603 2530,665 r270 top value=0
R37 "RC0603JR-070RL" 0603 575,1140 r0 top value=0
R38 "RC0603JR-070RL" 0603 540,515 r270 top value=0
R39 "RC0603JR-070RL" 0603 2530,530 r270 top value=0
R40 "RC0603JR-070RL" 0603 3445,1000 r0 top value=0
R41 "RC0603JR-070RL" 0603 1995,420 r0 top value=0
R42 "RC0603JR-070RL" 0603 1300,660 r90 top value=0
R43 "RC0603JR-070RL" 0603 1220,330 r270 top value=0
R44 "RC0603JR-070RL" 0603 1130,330 r90 top value=0
R45 "RC0603JR-070RL" 0603 1370,120 r180 top value=0
R46 "RC0603JR-070RL" 0603 455,940 r270 top value=0
R47 "RC0603JR-070RL" 0603 620,515 r270 top value=0
R48 "RC0603JR-070RL" 0603 1535,193.5 r270 top value=0
R49 "RC0603JR-070RL" 0603 2455,530 r270 top value=0
R50 "RC0603JR-070RL" 0603 1200,193.5 r90 top value=0
R51 "RC0603JR-070RL" 0603 1370,385 r180 top value=0
R52 "RC0603JR-070RL" 0603 1570,385 r180 top value=0
TP1 "+12 V" Keystone5013 1490.01,1981.13 r0 top
TP2 "GND" Keystone5011 365,1480 r90 top
TP3 "GND" Keystone5011 3160,1595 r90 top
TP4 "-12 V" Keystone5013 2090.01,1981.13 r0 top
TP5 "+15 V" Keystone5013 2675,1986.21 r0 top
TP6 "-15 V" Keystone5013 3275,1986.21 r0 top
TP7 "IN_TP" Keystone5013 1300,815 r0 top
TP8 "-5 V" Keystone5013 1165,1986.13 r0 top
TP9 "+5 V" Keystone5013 565,1986.13 r0 top
U1 "OPA2810DGK" DGK0008A_N 570,865 r270 top
U2 "OPA2810DGK" DGK0008A_N 2555,950 r270 top
U3 "BUF634U/2K5" D0008A_N 1035,975 r0 top
U4 "BUF634U/2K5" D0008A_N 2995,1025 r0 top
U7 "VCA821IDGST" DGS0010A_L 1370,245 r0 top
ZZ1 "This Assembly Note is for PCB labels only" AssemblyNoteLabel 185,3938 r0 top
ZZ2 "These assemblies are ESD sensitive, ESD precautions shall be observed." AssemblyNote 185,3829.11 r0 top
ZZ3 "These assemblies must be clean and free from flux and all contaminants. Use of no clean flux is not acceptable." AssemblyNote 185,3740.56 r0 top
ZZ4 "These assemblies must comply with workmanship standards IPC-A-610 Class 2, unless otherwise specified." AssemblyNote 185,3652 r0 top

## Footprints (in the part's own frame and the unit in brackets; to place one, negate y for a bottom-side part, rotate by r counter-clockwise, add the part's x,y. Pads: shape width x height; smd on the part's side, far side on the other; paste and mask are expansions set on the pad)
0402 [mm] "0402 from SM-752 data"
  rect 0.8x0.6 smd: 1(-0.6,0) 2(0.6,0)
  silkscreen extent -1.22,-0.52 1.22,0.52, body extent -0.55,-0.3 0.55,0.3, height 0.6
0603 [mm] "0603 from SM-752 data"
  rect 1x0.95 smd: 1(-0.8,0) 2(0.8,0)
  silkscreen extent -1.52,-0.69 1.52,0.69, body extent -0.87,-0.47 0.87,0.47, height 1
0805 [mm] "0805 from SM-752 data"
  rect 1.3x1.5 smd: 1(-0.85,0) 2(0.85,0)
  silkscreen extent -1.72,-0.97 1.72,0.97, body extent -1.1,-0.72 1.1,0.72, height 1.45
0805_HV [mil] "0805 with 30mil clearance between pads"
  rect 50x63 smd: 1(-40,0) 2(40,0)
  silkscreen extent -74,-40 74,40, body extent -43,-29 43,29, height 57
1210 [mm] "1210 from SM-752 data"
  rect 1.3x2.7 smd: 1(-1.45,0) 2(1.45,0)
  silkscreen extent -2.32,-1.57 2.32,1.57, body extent -1.7,-1.35 1.7,1.35, height 1.35
2010 [mm] "Chip Capacitor, Body 5.08x2.54mm, IPC Medium Density"
  rect 1.6x2.7 smd: 1(-2.3,0) 2(2.3,0)
  silkscreen extent -3.42,-1.65 3.42,1.65, body extent -2.73,-1.45 2.73,1.45, height 1.66
AssemblyNote [mil] "Assembly Note"
AssemblyNoteLabel [mil] "Assembly Note for PCB Labels"
CE_Mark_5mm [mil] "Minimum text height for CE Mark"
  silkscreen extent -138,-98 138,98
CONN_PEC02SAAN [mm] "SULLINS"
  rrect7% 1.5x1.5 hole 1.016: 1(-1.27,0)
  round 1.5 hole 1.016: 2(1.27,0)
  silkscreen extent -2.54,-1.52 2.54,1.27, body extent -2.54,-1.27 2.54,1.27, height 8.38
D0008A_N [mm] "SOIC, 8-Leads, Body 4.9x3.9mm, Pitch 1.27mm, IPC Medium Density"
  oval 1.45x0.6 smd: 1(-2.725,1.905) 2(-2.725,0.635) 3(-2.725,-0.635) 4(-2.725,-1.905) 5(2.725,-1.905) 6(2.725,-0.635) 7(2.725,0.635) 8(2.725,1.905)
  silkscreen extent -3.3,-2.5 0.9,2.5, body extent -3,-2.45 3,2.45, height 1.63
DGK0008A_N [mm] "TSOP, 8-Leads, Body 3x3mm, Pitch 0.65mm, IPC Medium Density"
  oval 1.35x0.45 smd: 1(-2.225,0.975) 2(-2.225,0.325) 3(-2.225,-0.325) 4(-2.225,-0.975) 5(2.225,-0.975) 6(2.225,-0.325) 7(2.225,0.325) 8(2.225,0.975)
  silkscreen extent -2.75,-1.55 0.95,1.55, body extent -2.45,-1.5 2.45,1.5, height 0.96
DGS0010A_L [mm] "TSSOP, 10-Leads, Body 3x3mm, Pitch 0.5mm, IPC High Density"
  oval 1.15x0.25 smd: 1(-2.125,1) 2(-2.125,0.5) 3(-2.125,0) 4(-2.125,-0.5) 5(-2.125,-1) 6(2.125,-1) 7(2.125,-0.5) 8(2.125,0) 9(2.125,0.5) 10(2.125,1)
  silkscreen extent -2.65,-1.55 0.9,1.55, body extent -2.45,-1.5 2.45,1.5, height 0.96
FCC_disclaimer [mil]
Fiducial10-20 [mm]
  round 1 smd mask+0.5: 1(0,0)
  L01_TOP keep-out circle w1.178: c0,0 r0.5
Johnson_142-0701-80x [mil] "Johnson Components recommended land pattern"
  rect 90x200 smd: 1(0,0)
  rect 95x200 smd: 2(-172.5,0) 3(172.5,0)
  round 38 hole 18: 2(-172.5,-135) 3(172.5,-135)
  rect 95x200 smd far side: 4(-172.5,0) 5(172.5,0)
  L01_TOP lines w18: 172.5,-135 172.5,0 ; -172.5,-135 -172.5,0
  L04_BOT lines w18: 172.5,-135 172.5,0 ; -172.5,-135 -172.5,0
  silkscreen extent -235,-170 235,100, body extent -190,-92 190,480, height 165
Keystone5011 [mil] "Keystone Multipurpose loops"
  round 87 hole 63: 1(0,0)
  silkscreen extent -70,-70 70,70, body extent -63,-63 63,62, height 319
Keystone5013 [mil] "Keystone Multipurpose loops"
  round 87 hole 63: 1(0,0)
  silkscreen extent -70,-70 70,70, body extent -63,-63 63,62, height 319
Keystone_1902C [mil] "Hex Standoff, 4-40 threaded, nylon"
  round 1 on Mech4: 0(0,0)
  body extent -145,-126 146,126, height 501
Label_650x200 [mil] "Thermal Transfer Label"
  round 1 on Mech13: 0(0,0)
  silkscreen extent -325,-100 325,100, body extent -325,-100 325,100, height 1
"NY PMS 440 0025 PH" [mm] "4-40 nylon screw and mounting hole"
  round 8 hole 3.2: 1(0,0)
  body extent -3.3,-3.3 3.3,3.3, height 2.69
Phoenix_1759020 [mm] "Header (Shrouded), 5.08mm, 3x1, R/A, TH"
  rect 1.9x1.9 hole 1.4: 1(-5.08,0)
  round 1.9 hole 1.4: 2(0,0) 3(5.08,0)
  silkscreen extent -8.1,-10 7.62,2, body extent -7.62,-10 7.62,2, height 9.1
SOD-123 [mm] "On Semi recommended land pattern"
  rect 0.915x1.22 smd: 1(-1.637,0) 2(1.637,0)
  silkscreen extent -2.74,-1.17 2.03,1.17, body extent -1.93,-0.9 1.93,0.9, height 1.35
TI_Stacked_Overlay_Small [mil]
  silkscreen extent -418,-98 418,98
WEEE_Minimum [mil] "WEEElie bin"
  silkscreen extent -95,-172 99,104

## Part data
C1 C10 C11 C12 C25 C26 C27: library part CMP-0006480-2, "CAP, CERM, 5 pF, 50 V, +/- 5%, C0G/NP0, 0402", Cap_Case=0402, Manufacturer=MuRata, Supplier Part Number 1=490-5875-1-ND, TempCo=C0G/NP0, Tolerance_%=5%, Value1=Unknown, Value2=50V, ValueDisplayed=5pF
C2 C5 C6 C9 C23 C32 C33 C36 C38 C40 C42 C44: library part CMP-0007052-4, "CAP, CERM, 1 uF, 35 V, +/- 10%, X7R, 0603", Cap_Case=0603, Manufacturer=TDK, Supplier Part Number 1=445-7414-1-ND, TempCo=X7R, Tolerance_%=10%, Value1=Unknown, Value2=35V, ValueDisplayed=1uF
C3 C4 C7 C8 C15 C17 C19 C21 C41 C43: library part CMP-0007434-4, "CAP, CERM, 0.1 uF, 50 V, +/- 10%, X7R, 0603", Cap_Case=0603, Manufacturer=MuRata, Supplier Part Number 1=490-1519-1-ND, TempCo=X7R, Tolerance_%=10%, Value1=Unknown, Value2=50V, ValueDisplayed=0.1uF
C13: library part Capacitor, "CAP, CERM, xxxF, xxV, [TempCo], xx%, [PackageReference]", Alternate Manufacturer=-
C14 C16 C18 C20 C22 C24 C34 C35 C37 C39: library part CMP-0008273-1, "CAP, CERM, 10 uF, 35 V, +/- 10%, X6S, 0805", Cap_Case=0805, Manufacturer=MuRata, Supplier Part Number 1=490-10504-1-ND, TempCo=X6S, Tolerance_%=10%, Value1=Unknown, Value2=35V, ValueDisplayed=10uF
D1 D2 D5 D6: library part CMP-0005744-4, "Diode, Zener, 14 V, 500 mW, SOD-123", Manufacturer="ON Semiconductor", Power_W=500mW, Value1=0.5W
D3 D4: library part CMP-0005747-4, "Diode, Zener, 18 V, 500 mW, SOD-123", Manufacturer="ON Semiconductor", Power_W=500mW, Value1=0.5W
FID1 FID2 FID3: library part CMP-0077181-1, "Fiducial mark.  There is nothing to buy or mount.", Manufacturer=N/A
H1 H2 H3 H4: library part CMP-0003617-1, "Machine Screw, Round, #4-40 x 1/4, Nylon, Philips panhead", Manufacturer="B&F Fastener Supply", Supplier Part Number 1=H542-ND
H5 H6 H7 H8: library part CMP-0003610-1, "Standoff, Hex, 0.5\"L #4-40 Nylon", Manufacturer=Keystone, Supplier Part Number 1=36-1902C-ND
J1 J2 J3 J4 J5 J6 J7 J10 J14 J17 J18: library part CMP-0002337-1, "Header, 100mil, 2x1, Tin, TH", Color=Black, Current_A=3A, Manufacturer="Sullins Connector Solutions", Supplier Part Number 1=S1012E-02-ND, Voltage_V=1.8kV
J8 J11 J12 J13 J21: library part CMP-0055821-1, "Connector, End launch SMA, 50 ohm, SMT", Manufacturer="Cinch Connectivity", PartNumber=142-0701-806, Supplier Part Number 1=J716-ND
J9: library part CMP-0055821-1, "Connector, End launch SMA, 50 ohm, SMT", Manufacturer="Cinch Connectivity", Supplier Part Number 1=J716-ND
J15 J16 J20: library part CMP-0055548-1, "Header (Shrouded), 5.08mm, 3x1, Tin, R/A, TH", Color=Green, Current_A=12A, Manufacturer="Phoenix Contact", Supplier Part Number 1=277-1096-ND, Voltage_V=320V
L1: library part Inductor, "Inductor, [Technology], [Material], xxuH, xxA, x.xx ohm, [MountType]", Alternate Manufacturer=-
LBL1: library part CMP-0003625-1, "Thermal Transfer Printable Labels, 0.650\" W x 0.200\" H - 10,000 per roll", Manufacturer=Brady, Supplier Part Number 1=97C5133
Logo1: library part CMP-0074844-1
Logo2: library part CMP-0074838-1, "Texas Instrument Corporate Signature"
Logo3: library part CMP-0074847-1, "FCC_disclaimer"
Logo4: library part CMP-0074769-1
R1 R2 R3 R4 R8 R9 R15 R16 R17 R18 R19 R20 R22 R23 R24 R25 R26 R27 R28 R29 R30 R31 R32 R33 R34 R35 R36 R37 R38 R39 R40 R41 R42 R43 R44 R45 R46 R47 R48 R49 R50 R51 R52: library part CMP-0025885-5, "RES, 0, 5%, 0.1 W, 0603", Manufacturer=Yageo, Power_W=100mW, Supplier Part Number 1=311-0.0GRCT-ND, TempCo="200 ppm/C", Tolerance_%=5%, Value2=0.1W, Value_Code=0000, ValueDisplayed=0
R5 R10: library part CMP-0026814-1, "RES, 100, 0.1%, 0.063 W, 0402", Manufacturer="Susumu Co Ltd", Power_W=63mW, Supplier Part Number 1=RG10P100BCT-ND, TempCo="25 ppm/C", Tolerance_%=0.1%, Value2=0.063W, Value_Code=100R, ValueDisplayed=100
R6 R11 R12 R13: library part CMP-0026813-1, "RES, 5.00 k, 0.1%, 0.05 W, 0402", Manufacturer=Vishay-Dale, Power_W=50mW, Supplier Part Number 1=541-1901-1-ND, TempCo="25 ppm/C", Tolerance_%=0.1%, Value2=0.05W, Value_Code=5k00, ValueDisplayed=5.00k
R7 R21: library part CMP-0023405-3, "RES, 100 k, 0.1%, 0.1 W, 0603", Manufacturer="Susumu Co Ltd", Power_W=100mW, Supplier Part Number 1=RG16P100KBCT-ND, TempCo="25 ppm/C", Tolerance_%=0.1%, Value2=0.1W, Value_Code=100k
R14: library part Resistor, "RES, xxx ohm, x%, xW, [PackageReference]", Alternate Manufacturer=-
TP1 TP4 TP5 TP6 TP7 TP8 TP9: library part 5013, "Test Point, Multipurpose, Orange, TH", Color=Orange, Manufacturer=Keystone, Supplier Part Number 1=36-5013-ND
TP2 TP3: library part 5011, "Test Point, Multipurpose, Black, TH", Color=Black, Manufacturer=Keystone, Supplier Part Number 1=36-5011-ND
U1 U2: library part CMP-0013308-3, "OPA2810DGK, DGK0008A (VSSOP-8)", Alternate Manufacturer="Texas Instruments"
U3 U4: library part CMP-0082445-1, "250mA High-Speed Buffer, D0008A (SOIC-8)", Alternate Manufacturer="Texas Instruments", Alternate PartNumber=BUF634U, Operating Temperature Range="-40 to 125 C", Rating=Catalog
U7: library part CMP-0033443-1, "Wideband, > 40 dB Adjust Range, Linear in dB Variable Gain Amplifier, -40 to 85 degC, 10-pin SOP (DGS10), Green (RoHS & no Sb/Br)", Manufacturer="Texas Instruments"
ZZ1: library part CMP-0003616-3
ZZ2: library part CMP-0077236-1
ZZ3: library part CMP-0077237-1
ZZ4: library part CMP-0077238-1

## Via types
v1: diameter 24, hole 12, L01_TOP to L04_BOT, tented both sides, 170 vias

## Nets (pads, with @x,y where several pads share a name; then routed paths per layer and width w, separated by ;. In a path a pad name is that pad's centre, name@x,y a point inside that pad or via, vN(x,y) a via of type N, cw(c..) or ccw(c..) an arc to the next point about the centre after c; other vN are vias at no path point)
BUF1_V+: C14.1 C15.1 R27.1 U3.7 | length 284
  L01_TOP w24: R27.1@1141.5,1135 C14.1@1225,1135 1233.5,1126.5 C15.1@1233.5,1050 1183.5,1000 U3.7@1142.28,1000
BUF1_V-: C18.2 C19.2 R12.2 R33.2 U3.4 | length 592.3
  L01_TOP w24: R33.2@927.71,605 919.21,613.5 C18.2@919.21,705 919.21,806.5 C19.2@927.71,815 U3.4@927.71,900 973,900 992,919 992,1112.96 R12.2@974.96,1130
BUF2_V+: C16.1 C17.1 R28.1 U4.7 | length 284
  L01_TOP w24: R28.1@3101.5,1185 C16.1@3185,1185 3185,1108.51 C17.1@3193.51,1100 3143.5,1050 U4.7@3102.28,1050
BUF2_V-: C20.2 C21.2 R11.2 R34.2 U4.4 | length 607.6
  L01_TOP w24: R34.2@2887.72,655.01 2879.22,663.51 C20.2@2879.22,755.01 2879.22,841.5 C21.2@2887.72,850 U4.4@2887.72,950 2938,950 2961,973 2961,1158.96 R11.2@2934.96,1185
GND: C2.2 C3.2 C4.2 C5.2 C6.2 C7.2 C8.2 C9.2 C14.2 C15.2 C16.2 C17.2 C18.1 C19.1 C20.1 C21.1 C22.2 C23.2 C24.2 C32.1 C33.1 C34.2 C35.2 C36.1 C37.2 C38.1 C39.2 C40.1 C41.2 C42.1 C43.2 C44.1 D1.2 D2.1 D3.2 D4.1 D5.2 D6.1 J8.2 J8.3 J8.4 J8.5 J9.2 J9.3 J9.4 J9.5 J11.2 J11.3 J11.4 J11.5 J12.2 J12.3 J12.4 J12.5 J13.2 J13.3 J13.4 J13.5 J15.2 J16.2 J20.2 J21.2 J21.3 J21.4 J21.5 R19.1 R20.1 R24.1 R25.1 R31.1 R44.2 R46.1 R48.2 R50.1 TP2.1 TP3.1 U2.3 U7.10 | length 1429.8
  L01_TOP w10: U7.10@1453.66,284.37 v1(1453.66,315.66)
  L01_TOP w17.7: v1(698,1035) R19.1@743.5,1035 ; U2.3@2542.2,1037.6 v1(2542.2,1092.8)
  L01_TOP w24: v1(353,1047.6) C4.2@398.5,1047.6 ; v1(353,1125) C5.2@398.5,1125 ; v1(409.5,971.5) R46.1@455,971.5 ; R31.1@455,840.39 v1(498.61,840.39) ; C3.2@680,840.39 v1(680,885.9) ; C2.2@755,840.39 v1(755,885.9) ; C19.1@990.7,815 v1(1036.21,815) ; C18.1@999.21,705 v1(1050,705) ; R44.2@1130,361.5 v1(1130,407) ; v1(1200,116.5) R50.1@1200,162.01 ; C15.2@1296.5,1050 v1(1342,1050) ; C14.2@1305,1135 v1(1355.79,1135) ; v1(1535,116.5) R48.2@1535,162.01 ; C9.2@2365,1100.59 v1(2365,1146.09) ; R25.1@2445,925.39 v1(2483,925.39) ; C8.2@2445,1100.59 v1(2445,1146.09) ; v1(2530,298) R24.1@2530,343.5 ; v1(2619.5,925.39) C7.2@2665,925.39 ; C6.2@2740,925.39 v1(2785.51,925.39) ; R20.1@2766.5,1146.5 v1(2766.5,1192) ; C21.1@2950.71,850 v1(2996.21,850) ; C20.1@2959.22,755.01 v1(3010.01,755.01) ; C17.2@3256.5,1100 v1(3302,1100) ; C16.2@3265,1185 v1(3315.79,1185)
  L04_BOT w24: v1(1286.06,152.48) C42.1@1334.57,152.48 ; C41.2@1335,381.5 v1(1335,430) ; C43.2@1405,381.5 v1(1405,430) ; C44.1@1405.43,152.48 v1(1453.94,152.48)
  other v1: 2400,100 3250,200 2750,300 1555,315 600,350 2200,350 3150,350 413.95,359.66 2600,500 313.95,509.66 2750,550 3050,550 1800,650 1500,800 1900,800 3100,800 3200,800 3400,800 2266,815 1500,1050 3600,1050 850,1100 1900,1100 1500,1200 750,1250 450,1295 100,1350 2455,1390 1500,1400 2825,1400 3200,1400 3350,1400 1900,1450 2150,1450 550,1487.32 700,1500 2450,1550 2750,1600 3000,1600 3400,1600 2470,1675 450,1700 700,1700 1735,1740 1785,1740 1835,1740 810,1745 860,1745 910,1745 2920,1745.09 2970,1745.09 3020,1745.09 100,1750 1735,1790 1785,1790 1835,1790 810,1795 860,1795 910,1795 2920,1795.09 2970,1795.09 3020,1795.09 3550,1800 1785,1840 860,1845 2970,1845.09 150,1950 350,1950 3550,1950 350,2100 3550,2100 2300,2200 500,2450 2400,2450
NetC1_1: C1.1 C12.1 J1.2 J2.2 J3.2 R9.2 R18.2 R40.1 | length 2003.5
  L01_TOP w10: C1.1@2413.62,1730 2620,1730 2655,1695 J1.2@2655,1620 J2.2@2655,1465 ; C12.1@2655,1138.62 J3.2@2655,1316.98 J2.2@2655,1465 ; R18.2@3331.5,1000 R40.1@3413.5,1000 3413.5,1187.5 3286,1315 R9.2@3046.5,1315 3046.5,1397.5 2979,1465 J2.2@2655,1465
NetC1_2: C1.2 C10.2 C13.1 J4.2 J6.2 L1.2 R5.1 R6.1 R7.1 R14.2 R23.1 R26.1 U2.2 | length 2154
  L01_TOP w10: J6.2@2167,1315 2168.98,1316.98 C10.2@2366.38,1316.98 ; L1.2@2174.09,950 2268,950 2292.61,925.39 R23.1@2365,925.39 2410.61,971 2545,971 2567.8,993.8 U2.2@2567.8,1037.6 ; 2207.55,702.91 2213.97,696.5 R26.1@2365,696.5 ; R7.1@2358.5,1236.98 2358.5,1309.11 C10.2@2366.38,1316.98 ; C1.2@2366.38,1730 R5.1@2366.38,1620 R6.1@2366.38,1465 C10.2@2366.38,1316.98
  L01_TOP w30: J6.2@2167,1315 J4.2@2167,1139 2167,957.09 L1.2@2174.09,950 2174.09,783.62 R14.2@2150.46,760 2207.55,702.91 C13.1@2207.55,530
NetC2_1: C2.1 C3.1 R1.1 U1.8 | length 227.5
  L01_TOP w17.7: U1.8@608.39,777.4 C3.1@680,777.4
  L01_TOP w24: C3.1@680,777.4 C2.1@755,777.4 R1.1@755,696.5
NetC4_1: C4.1 C5.1 R2.1 U1.4 | length 286.4
  L01_TOP w17.7: C4.1@461.5,1047.6 531.61,977.48 U1.4@531.61,952.6
  L01_TOP w37: C4.1@461.5,1047.6 C5.1@461.5,1125 R2.1@461.5,1210
NetC6_1: C6.1 C7.1 R3.1 U2.8 | length 228.6
  L01_TOP w17.7: U2.8@2593.39,862.4 C7.1@2665,862.4
  L01_TOP w24: C7.1@2665,862.4 C6.1@2740,862.4 R3.1@2740,780.39
NetC8_1: C8.1 C9.1 R4.1 U2.4 | length 231.6
  L01_TOP w17.7: C8.1@2445,1037.6 U2.4@2516.61,1037.6
  L01_TOP w24: R4.1@2285,1037.6 C9.1@2365,1037.6 C8.1@2445,1037.6
NetC10_1: C10.1 J3.1 R7.2 | length 224.6
  L01_TOP w10: R7.2@2421.5,1236.98 2421.5,1309.11 C10.1@2413.62,1316.98 J3.1@2555,1316.98
NetC11_1: C11.1 R8.1 R15.1 U1.1 | length 692.4
  L01_TOP w10: R15.1@743.5,952.6 U1.1@608.39,952.6 608.39,991.39 670,1053 C11.1@670,1092.76 720.76,1092.76 873,1245 R8.1@998.5,1245
NetC11_2: C11.2 C25.1 J14.1 R8.2 R16.2 R37.2 R42.2 TP7.1 | length 1748.1
  L01_TOP w10: C25.1@598.62,1065 606.5,1072.87 R37.2@606.5,1140 C11.2@670,1140 670,1275 709,1314 1037,1314 1061.5,1289.5 R8.2@1061.5,1245 1346,1245 1435,1156 J14.1@1435,950 R16.2@1301.5,950 1301.5,816.5 TP7.1@1300,815 R42.2@1300,691.5
NetC12_2: C12.2 R9.1 R17.1 U2.1 | length 664.9
  L01_TOP w10: U2.1@2593.39,1037.6 2656,1037.6 ; R17.1@2703.5,1000 2665.91,1037.6 2656,1037.6 ; R9.1@2983.5,1315 2804,1315 2711,1222 2711,1113 2689.38,1091.38 C12.2@2655,1091.38 2655,1038.6 2656,1037.6
NetC13_2: C13.2 J4.1 J5.2 J6.1 J7.2 J10.2 L1.1 R14.1 R41.2 | length 1374.7
  L01_TOP w10: J7.2@1920,950 L1.1@2059.91,950
  L01_TOP w30: J10.2@1870,530 C13.2@2026.45,530 ; J5.2@1920,1315 J6.1@2067,1315 J4.1@2067,1139 2067,957.09 L1.1@2059.91,950 2059.91,783.62 R14.1@2083.54,760 2026.45,702.91 C13.2@2026.45,530 ; R41.2@2026.5,420 2026.45,420.05 C13.2@2026.45,530
NetC25_2: C25.2 R37.1 U1.2 | length 203.7
  L01_TOP w10: R37.1@543.5,1140 543.5,1072.87 C25.2@551.38,1065 551.38,1023.62 582.8,992.2 U1.2@582.8,952.6
NetC26_2: C26.2 R36.1 U2.6 | length 244.2
  L01_TOP w10: C26.2@2460,688.62 2467.87,696.5 R36.1@2530,696.5 2530,779 2542.2,791.2 U2.6@2542.2,862.4
NetC27_2: C27.2 R35.1 U1.6 | length 171.3
  L01_TOP w10: C27.2@470,678.62 477.87,686.5 R35.1@540,686.5 557.2,703.7 U1.6@557.2,777.4
NetJ1_1: J1.1 R5.2 | length 141.4
  L01_TOP w10: R5.2@2413.62,1620 J1.1@2555,1620
NetJ2_1: J2.1 R6.2 | length 141.4
  L01_TOP w10: R6.2@2413.62,1465 J2.1@2555,1465
NetJ5_1: J5.1 R10.2 | length 126.4
  L01_TOP w30: R10.2@1693.62,1315 J5.1@1820,1315
NetJ7_1: J7.1 R13.2 | length 126.4
  L01_TOP w10: R13.2@1693.62,950 J7.1@1820,950
NetJ8_1: J8.1 R40.2 | length 613
  L01_TOP w10: R40.2@3476.5,1000 3476.5,1411.5 3520,1455 J8.1@3660,1455
NetJ9_1: J9.1 R46.2 U1.3 | length 497.3
  L01_TOP w10: J9.1@100,915 448.5,915 R46.2@455,908.5 545.71,908.5 557.2,920 U1.3@557.2,952.6
NetJ10_1: J10.1 R21.2 | length 118.5
  L01_TOP w30: R21.2@1651.5,530 J10.1@1770,530
NetJ11_1: J11.1 J12.1 R24.2 R39.2 | length 1643.9
  L01_TOP w10: R39.2@2530,498.5 R24.2@2530,406.5 2835,406.5 ; J12.1@2835,100 2835,406.5 ; J11.1@3660,685 3310,685 3031.5,406.5 2835,406.5
NetJ13_1: J13.1 R38.2 | length 566.9
  L01_TOP w10: R38.2@540,483.5 623.5,400 735,400 825,310 J13.1@825,100
NetJ14_2: J14.2 R10.1 R13.1 R21.1 | length 920.4
  L01_TOP w10: J14.2@1535,950 R13.1@1646.38,950
  L01_TOP w30: R21.1@1588.5,530 1588.5,730.5 1646.38,788.38 R13.1@1646.38,950 R10.1@1646.38,1315
NetJ21_1: J21.1 R52.1 | length 515.6
  L01_TOP w10: R52.1@1601.5,385 v1(1650,385) ; J21.1@1925.01,105 v1(1925.01,234.99)
  L04_BOT w10: v1(1650,385) 1775,385 v1(1925.01,234.99)
NetR11_1: R11.1 U4.1 | length 85
  L01_TOP w24: U4.1@2887.72,1100 R11.1@2887.72,1185
NetR12_1: R12.1 U3.1 | length 80
  L01_TOP w24: U3.1@927.71,1050 R12.1@927.71,1130
NetR15_2: R15.2 R19.2 U3.3 | length 204.7
  L01_TOP w10: R19.2@806.5,1035 R15.2@806.5,952.6 809.1,950 U3.3@927.71,950
NetR16_1: R16.1 U3.6 | length 96.2
  L01_TOP w10: U3.6@1142.28,950 R16.1@1238.5,950
NetR17_2: R17.2 R20.2 U4.3 | length 204.7
  L01_TOP w10: R20.2@2766.5,1083.5 R17.2@2766.5,1000 U4.3@2887.72,1000
NetR18_1: R18.1 U4.6 | length 166.2
  L01_TOP w10: U4.6@3102.28,1000 R18.1@3268.5,1000
NetR22_1: R22.1 U2.7 | length 181.3
  L01_TOP w10: U2.7@2567.8,862.4 2567.8,797.2 2605,760 R22.1@2605,696.5
NetR23_2: R23.2 R25.2 U2.5 | length 151.6
  L01_TOP w17.7: R25.2@2445,862.4 U2.5@2516.61,862.4
  L01_TOP w24: R23.2@2365,862.4 R25.2@2445,862.4
NetR29_1: R29.1 U1.7 | length 106.3
  L01_TOP w10: U1.7@582.8,777.4 582.8,723.7 R29.1@620,686.5
NetR30_1: R30.1 R32.1 R41.1 R42.1 | length 1941.8
  L01_TOP w10: R32.1@379.5,687 v1(423.1,687) ; R32.1@380,686.5 336.39,730.1 336.39,796.79 R30.1@380,840.39 ; v1(1256.39,628.5) R42.1@1300,628.5 1468.5,460 1923.5,460 R41.1@1963.5,420
  L04_BOT w10: v1(423.1,687) 520.1,590 805,590 874,659 1225.9,659 v1(1256.39,628.5)
NetR30_2: R30.2 R31.2 U1.5 | length 151.6
  L01_TOP w17.7: R31.2@455,777.4 U1.5@531.61,777.4
  L01_TOP w24: R30.2@380,777.4 R31.2@455,777.4
NetR45_1: R45.1 U7.6 | length 129.5
  L01_TOP w10: R45.1@1401.5,120 1401.5,191.5 1415.63,205.63 U7.6@1453.66,205.63
NetR45_2: R45.2 U7.5 | length 128.9
  L01_TOP w10: U7.5@1286.34,205.63 1323.37,205.63 1338.5,190.5 R45.2@1338.5,120
NetR47_2: R47.2 R50.2 U7.4 | length 773.5
  L01_TOP w10: R47.2@620,483.5 864.5,483.5 1123,225 R50.2@1200,225 1200.32,225.32 U7.4@1286.34,225.32
NetR48_1: R48.1 R49.2 U7.7 | length 1114.9
  L01_TOP w10: U7.7@1453.66,225.32 R48.1@1534.68,225.32 ; R48.1@1535,225 R48.1@1534.68,225.32 ; R49.2@2455,498.5 2266.5,310 1619.37,310 R48.1@1534.68,225.32
NetR51_1: R51.1 R52.2 U7.9 | length 292.6
  L01_TOP w10: R51.1@1401.5,385 1495,385 ; U7.9@1453.66,264.69 1484.69,264.69 1495,275 1495,385 ; R52.2@1538.5,385 1495,385
NetR51_2: R51.2 U7.1 | length 122.2
  L01_TOP w10: U7.1@1286.34,284.37 1286.34,332.83 R51.2@1338.5,385
VCC1: C33.2 C34.1 D1.1 J15.1 J17.2 R1.2 R3.2 TP1.1 | length 1237.4
  L01_TOP w24: v1(709.5,679.01) v1(709.5,633.5) R1.2@755,633.5 ; v1(2694.5,717.4) R3.2@2740,717.4 v1(2785.5,717.4)
  L01_TOP w30: v1(1515,1740) 1515,1665 1555,1625 2190,1625 2250,1685 2250,1790 J17.2@2320,1860
  other v1: 1465,1740 1565,1740 1465,1790 1515,1790 1465,1840 1515,1840
VCC2: C22.1 C23.1 D3.1 J17.1 J20.1 R27.2 R28.2 TP5.1 | length 489.3
  L01_TOP w24: v1(1033,1135) R27.2@1078.5,1135 v1(1078.5,1180.5) ; v1(3038.51,1139.5) R28.2@3038.51,1185 v1(3038.51,1230.51)
  L01_TOP w30: J17.1@2420,1860 2546.21,1986.21 TP5.1@2675,1986.21
  other v1: 2650,1745.09 2700,1745.09 2750,1745.09 2650,1795.09 2700,1795.09 2650,1845.09 2700,1845.09
VCC3: C37.1 C38.2 C41.1 C42.2 D5.1 J16.1 R43.1 TP9.1 U7.2 | length 197.1
  L01_TOP w10: U7.2@1286.34,264.69 v1(1334.69,264.69)
  L01_TOP w24: R43.1@1220,361.5 v1(1265.5,361.5)
  L04_BOT w24: C42.2@1334.57,215.47 1334.57,264.57 v1(1334.69,264.69) 1335,265 C41.1@1335,318.5
  other v1: 540,1745 590,1745 640,1745 540,1795 590,1795 540,1845 590,1845
VEE1: C35.1 C36.2 D2.2 J15.3 J18.1 R2.2 R4.2 TP4.1 | length 453
  L01_TOP w24: v1(353,1210) R2.2@398.5,1210 v1(398.5,1255.5) ; v1(2238.5,1099.59) R4.2@2284,1099.59 ; R4.2@2284,1100.59 v1(2284,1146.09)
  L01_TOP w39.3: TP4.1@2090.01,1981.13 2221.13,1981.13 J18.1@2320,2080
  other v1: 2015.01,1740 2065.01,1740 2115.01,1740 2065.01,1790 2115.01,1790 2065.01,1840 2115.01,1840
